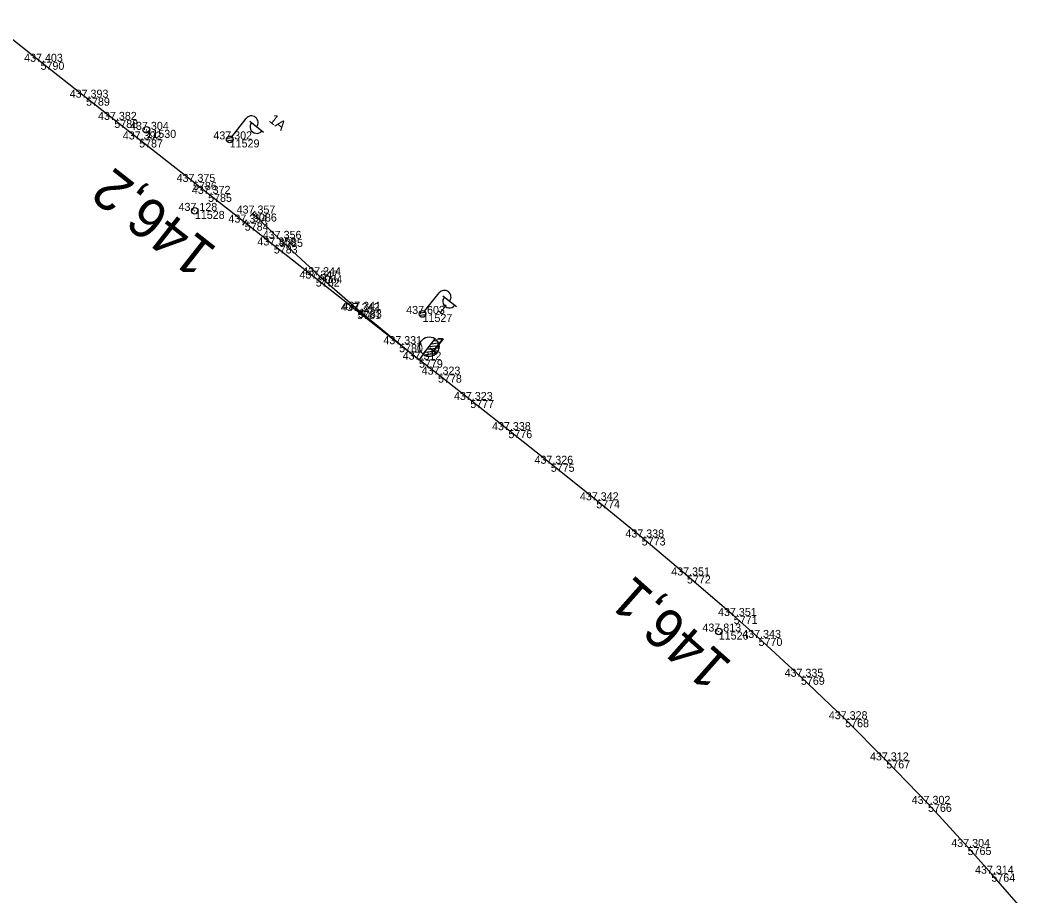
# Model space of a CAD drawing. Extents: x -654154 to -652650, y -1166925 to -1164904.
# Drawn here: x -652982.4 to -652831, y -1166166.6 to -1166035.5 of the extents above; entities that cross this region are included whole.
import ezdxf

# ---------------------------------------------------------------- set-up
doc = ezdxf.new("R2010")
doc.units = 0
for name, color, linetype in [('Vrstva 1', 7, 'Continuous'), ('Vrstva 2', 7, 'Continuous'), ('Vrstva 25', 7, 'Continuous'), ('Vrstva 50', 7, 'Continuous'), ('Vrstva 60', 7, 'Continuous'), ('Vrstva 61', 7, 'Continuous'), ('Vrstva 7', 7, 'Continuous')]:
    doc.layers.add(name, color=color, linetype=linetype)

msp = doc.modelspace()

# ---------------------------------------------------------------- linework, layer by layer
at = {"layer": 'Vrstva 1'}
msp.add_lwpolyline([(-652831.02, -1166169.95), (-652836.78, -1166163.34), (-652840.34, -1166159.33), (-652846.28, -1166152.87), (-652852.53, -1166146.36), (-652858.7, -1166140.19), (-652865.33, -1166133.83), (-652871.68, -1166128.01), (-652875.4, -1166124.72), (-652882.42, -1166118.65), (-652889.2, -1166112.96), (-652896.02, -1166107.39), (-652902.83, -1166101.92), (-652909.19, -1166096.88), (-652914.9, -1166092.36), (-652919.74, -1166088.56), (-652922.59, -1166086.33), (-652925.57, -1166084), (-652931.86, -1166079.04), (-652938.06, -1166074.17), (-652944.36, -1166069.21), (-652948.71, -1166065.79), (-652954.21, -1166061.48), (-652956.47, -1166059.69), (-652964.55, -1166053.33), (-652968.27, -1166050.4), (-652972.51, -1166047.07), (-652979.33, -1166041.69), (-652987.25, -1166035.46)], dxfattribs=at)
at = {"layer": 'Vrstva 2'}
for p, q in [((-652947.83, -1166064.79), (-652947.13, -1166064.07)), ((-652949.02, -1166066.18), (-652948.4, -1166065.39)), ((-652921.96, -1166085.52), (-652920.15, -1166083.22)), ((-652921.37, -1166084.77), (-652919.6, -1166084.56)), ((-652921.04, -1166084.35), (-652919.61, -1166084.18)), ((-652920.71, -1166083.94), (-652919.7, -1166083.82)), ((-652920.38, -1166083.52), (-652919.91, -1166083.46)), ((-652921.96, -1166085.52), (-652922.59, -1166086.33)), ((-652921.96, -1166085.52), (-652921.96, -1166085.52)), ((-652921.87, -1166085.58), (-652919.98, -1166085.36)), ((-652921.7, -1166085.19), (-652919.71, -1166084.95))]:
    msp.add_line(p, q, dxfattribs=at)
for points in [[(-652947.48, -1166064.43), (-652943.56, -1166068.22), (-652937.64, -1166073.67), (-652931.73, -1166078.85), (-652922.59, -1166086.33)], [(-652922.59, -1166086.33), (-652925.57, -1166084), (-652931.86, -1166079.04), (-652938.06, -1166074.17), (-652944.36, -1166069.21), (-652948.71, -1166065.79)]]:
    msp.add_lwpolyline(points, dxfattribs=at)
msp.add_circle((-652921.05, -1166084.37), 1.46, dxfattribs=at)
msp.add_arc((-652921.05, -1166084.37), 1.46, 231.7643, 51.7251, dxfattribs=at)
at = {"layer": 'Vrstva 25'}
for p, q in [((-652950.66, -1166052.93), (-652948.5, -1166050.18)), ((-652947.95, -1166050.61), (-652945.9, -1166052.22)), ((-652951.44, -1166053.14), (-652950.56, -1166053.04)), ((-652951.43, -1166053.52), (-652950.48, -1166053.4)), ((-652921.75, -1166079.07), (-652919.58, -1166076.32)), ((-652919.03, -1166076.76), (-652916.99, -1166078.37)), ((-652922.52, -1166079.28), (-652921.65, -1166079.18)), ((-652922.51, -1166079.66), (-652921.56, -1166079.55))]:
    msp.add_line(p, q, dxfattribs=at)
for centre in [(-652950.97, -1166053.32), (-652922.06, -1166079.47)]:
    msp.add_circle(centre, 0.5, dxfattribs=at)
for centre, start, end in [((-652947.71, -1166050.8), 321.7805, 141.7805), ((-652946.93, -1166051.42), 141.0779, 322.4831), ((-652918.79, -1166076.94), 321.7447, 141.7447), ((-652918.02, -1166077.57), 141.0421, 322.4473)]:
    msp.add_arc(centre, 1, start, end, dxfattribs=at)
at = {"layer": 'Vrstva 50'}
msp.add_line((-652963.51, -1166051.89), (-652963.41, -1166051.89), dxfattribs=at)
msp.add_circle((-652963.46, -1166051.89), 0.5, dxfattribs=at)
at = {"layer": 'Vrstva 60'}
for p, q in [((-652979.33, -1166041.69), (-652979.33, -1166041.69)), ((-652972.51, -1166047.07), (-652972.51, -1166047.07)), ((-652968.27, -1166050.4), (-652968.27, -1166050.4)), ((-652963.46, -1166051.89), (-652963.46, -1166051.89)), ((-652964.55, -1166053.33), (-652964.55, -1166053.33)), ((-652950.97, -1166053.32), (-652950.97, -1166053.32)), ((-652956.47, -1166059.69), (-652956.47, -1166059.69)), ((-652954.21, -1166061.48), (-652954.21, -1166061.48)), ((-652956.19, -1166064.03), (-652956.19, -1166064.03)), ((-652947.48, -1166064.43), (-652947.48, -1166064.43)), ((-652948.71, -1166065.79), (-652948.71, -1166065.79)), ((-652944.36, -1166069.21), (-652944.36, -1166069.21)), ((-652943.56, -1166068.22), (-652943.56, -1166068.22)), ((-652937.64, -1166073.67), (-652937.64, -1166073.67)), ((-652938.06, -1166074.17), (-652938.06, -1166074.17)), ((-652931.86, -1166079.04), (-652931.86, -1166079.04)), ((-652931.73, -1166078.85), (-652931.73, -1166078.85)), ((-652922.06, -1166079.47), (-652922.06, -1166079.47)), ((-652925.57, -1166084), (-652925.57, -1166084)), ((-652922.59, -1166086.33), (-652922.59, -1166086.33)), ((-652919.74, -1166088.56), (-652919.74, -1166088.56)), ((-652914.9, -1166092.36), (-652914.9, -1166092.36)), ((-652909.19, -1166096.88), (-652909.19, -1166096.88)), ((-652902.83, -1166101.92), (-652902.83, -1166101.92)), ((-652896.02, -1166107.39), (-652896.02, -1166107.39)), ((-652889.2, -1166112.96), (-652889.2, -1166112.96)), ((-652882.42, -1166118.65), (-652882.42, -1166118.65)), ((-652875.4, -1166124.72), (-652875.4, -1166124.72)), ((-652877.65, -1166127.06), (-652877.65, -1166127.06)), ((-652871.68, -1166128.01), (-652871.68, -1166128.01)), ((-652865.33, -1166133.83), (-652865.33, -1166133.83)), ((-652858.7, -1166140.19), (-652858.7, -1166140.19)), ((-652852.53, -1166146.36), (-652852.53, -1166146.36)), ((-652846.28, -1166152.87), (-652846.28, -1166152.87)), ((-652840.34, -1166159.33), (-652840.34, -1166159.33)), ((-652836.78, -1166163.34), (-652836.78, -1166163.34))]:
    msp.add_line(p, q, dxfattribs=at)
at = {"layer": 'Vrstva 7'}
for p, q in [((-652956.15, -1166064.06), (-652956.23, -1166064)), ((-652877.61, -1166127.09), (-652877.69, -1166127.03))]:
    msp.add_line(p, q, dxfattribs=at)
for centre in [(-652956.19, -1166064.03), (-652877.65, -1166127.06)]:
    msp.add_circle(centre, 0.5, dxfattribs=at)

# ---------------------------------------------------------------- texts
at = {"layer": 'Vrstva 2'}
msp.add_text('1', height=2.5, rotation=321.7447, dxfattribs=at).set_placement((-652921.28, -1166084.52))
at = {"layer": 'Vrstva 25'}
for s, rotation, p in [('1A', 321.7805, (-652945.19, -1166050.59)), ('1', 321.7447, (-652919.89, -1166078.95))]:
    msp.add_text(s, height=1.5, rotation=rotation, dxfattribs=at).set_placement(p)
at = {"layer": 'Vrstva 60'}
for s, p in [('5790', (-652979.33, -1166042.89)), ('5789', (-652972.51, -1166048.27)), ('5788', (-652968.27, -1166051.6)), ('11530', (-652963.46, -1166053.09)), ('5787', (-652964.55, -1166054.53)), ('11529', (-652950.97, -1166054.52)), ('5786', (-652956.47, -1166060.89)), ('5785', (-652954.21, -1166062.68)), ('11528', (-652956.19, -1166065.23)), ('9086', (-652947.48, -1166065.63)), ('5784', (-652948.71, -1166066.99)), ('5783', (-652944.36, -1166070.41)), ('9085', (-652943.56, -1166069.42)), ('9084', (-652937.64, -1166074.87)), ('5782', (-652938.06, -1166075.37)), ('5781', (-652931.86, -1166080.24)), ('9083', (-652931.73, -1166080.05)), ('11527', (-652922.06, -1166080.67)), ('5780', (-652925.57, -1166085.2)), ('5779', (-652922.59, -1166087.53)), ('5778', (-652919.74, -1166089.76)), ('5777', (-652914.9, -1166093.56)), ('5776', (-652909.19, -1166098.08)), ('5775', (-652902.83, -1166103.12)), ('5774', (-652896.02, -1166108.59)), ('5773', (-652889.2, -1166114.16)), ('5772', (-652882.42, -1166119.85)), ('5771', (-652875.4, -1166125.92)), ('11526', (-652877.65, -1166128.26)), ('5770', (-652871.68, -1166129.21)), ('5769', (-652865.33, -1166135.03)), ('5768', (-652858.7, -1166141.39)), ('5767', (-652852.53, -1166147.56)), ('5766', (-652846.28, -1166154.07)), ('5765', (-652840.34, -1166160.53)), ('5764', (-652836.78, -1166164.54))]:
    msp.add_text(s, height=1.2, dxfattribs=at).set_placement(p)
at = {"layer": 'Vrstva 61'}
for s, p in [('437.403', (-652981.79, -1166041.69)), ('437.393', (-652974.96, -1166047.07)), ('437.382', (-652970.71, -1166050.4)), ('437.304', (-652965.91, -1166051.89)), ('437.392', (-652967, -1166053.33)), ('437.302', (-652953.42, -1166053.32)), ('437.375', (-652958.93, -1166059.69)), ('437.372', (-652956.65, -1166061.48)), ('437.128', (-652958.64, -1166064.03)), ('437.357', (-652949.93, -1166064.43)), ('437.354', (-652951.16, -1166065.79)), ('437.358', (-652946.82, -1166069.21)), ('437.356', (-652946.01, -1166068.22)), ('437.344', (-652940.09, -1166073.67)), ('437.347', (-652940.51, -1166074.17)), ('437.342', (-652934.31, -1166079.04)), ('437.341', (-652934.08, -1166078.85)), ('437.603', (-652924.51, -1166079.47)), ('437.331', (-652927.93, -1166084)), ('437.312', (-652925.04, -1166086.33)), ('437.323', (-652922.19, -1166088.56)), ('437.323', (-652917.35, -1166092.36)), ('437.338', (-652911.64, -1166096.88)), ('437.326', (-652905.28, -1166101.92)), ('437.342', (-652898.47, -1166107.39)), ('437.338', (-652891.65, -1166112.96)), ('437.351', (-652884.78, -1166118.65)), ('437.351', (-652877.76, -1166124.72)), ('437.813', (-652880.1, -1166127.06)), ('437.343', (-652874.13, -1166128.01)), ('437.335', (-652867.78, -1166133.83)), ('437.328', (-652861.15, -1166140.19)), ('437.312', (-652854.98, -1166146.36)), ('437.302', (-652848.73, -1166152.87)), ('437.304', (-652842.79, -1166159.33)), ('437.314', (-652839.23, -1166163.34))]:
    msp.add_text(s, height=1.2, dxfattribs=at).set_placement(p)
at = {"layer": 'Vrstva 7'}
for s, rotation, p in [('146,2', 141.8746, (-652952.65, -1166069.73)), ('146,1', 138.4401, (-652875.42, -1166131.83))]:
    msp.add_text(s, height=6, rotation=rotation, dxfattribs=at).set_placement(p)

doc.saveas('drawing.dxf')
